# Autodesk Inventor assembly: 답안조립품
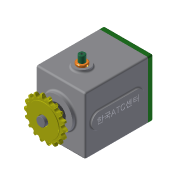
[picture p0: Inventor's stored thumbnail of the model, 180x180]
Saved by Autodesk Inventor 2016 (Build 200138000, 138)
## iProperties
Created: 2018-12
Part Number: 답안조립품
Material: 일반
Document SubType Name: Assembly
Designer: 3sil_cad019
Mass: 2992.99 g
Surface Area: 1968.34 cm^2
Volume: 816.163 cm^3
Density: 3.66715 g/cm^3
Author: 3sil_cad019
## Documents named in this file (16)
- C:\Users\3sil_cad019\Desktop\381208V1001\답안조립품.iam
- C:\Users\3sil_cad019\Desktop\381208V1001\본체.ipt
- C:\Users\3sil_cad019\Desktop\381208V1001\베어링 6003.ipt
- C:\Users\3sil_cad019\Desktop\381208V1001\볼트 M4 x 10.ipt
- C:\Users\3sil_cad019\Desktop\381208V1001\부시.ipt
- C:\Users\3sil_cad019\Desktop\381208V1001\서브 기어 축.ipt
- C:\Users\3sil_cad019\Desktop\381208V1001\스프로킷.ipt
- C:\Users\3sil_cad019\Desktop\381208V1001\슬라이더.ipt
- C:\Users\3sil_cad019\Desktop\381208V1001\오일 실 8 22 7.ipt
- C:\Users\3sil_cad019\Desktop\381208V1001\오일 실 17 32 8.ipt
- C:\Users\3sil_cad019\Desktop\381208V1001\커버.ipt
- C:\Users\3sil_cad019\Desktop\381208V1001\키 5 x 5 x 18.ipt
- C:\Users\3sil_cad019\Desktop\381208V1001\가변스프링.ipt
- C:\Users\3sil_cad019\Desktop\381208V1001\멈춤나사 M3x8.ipt
- C:\Users\3sil_cad019\Desktop\381208V1001\메인 기어 축.ipt
- C:\Users\3sil_cad019\Desktop\381208V1001\베어링 608.ipt
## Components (1 placed, 1 different names)
1. 가변스프링:1
